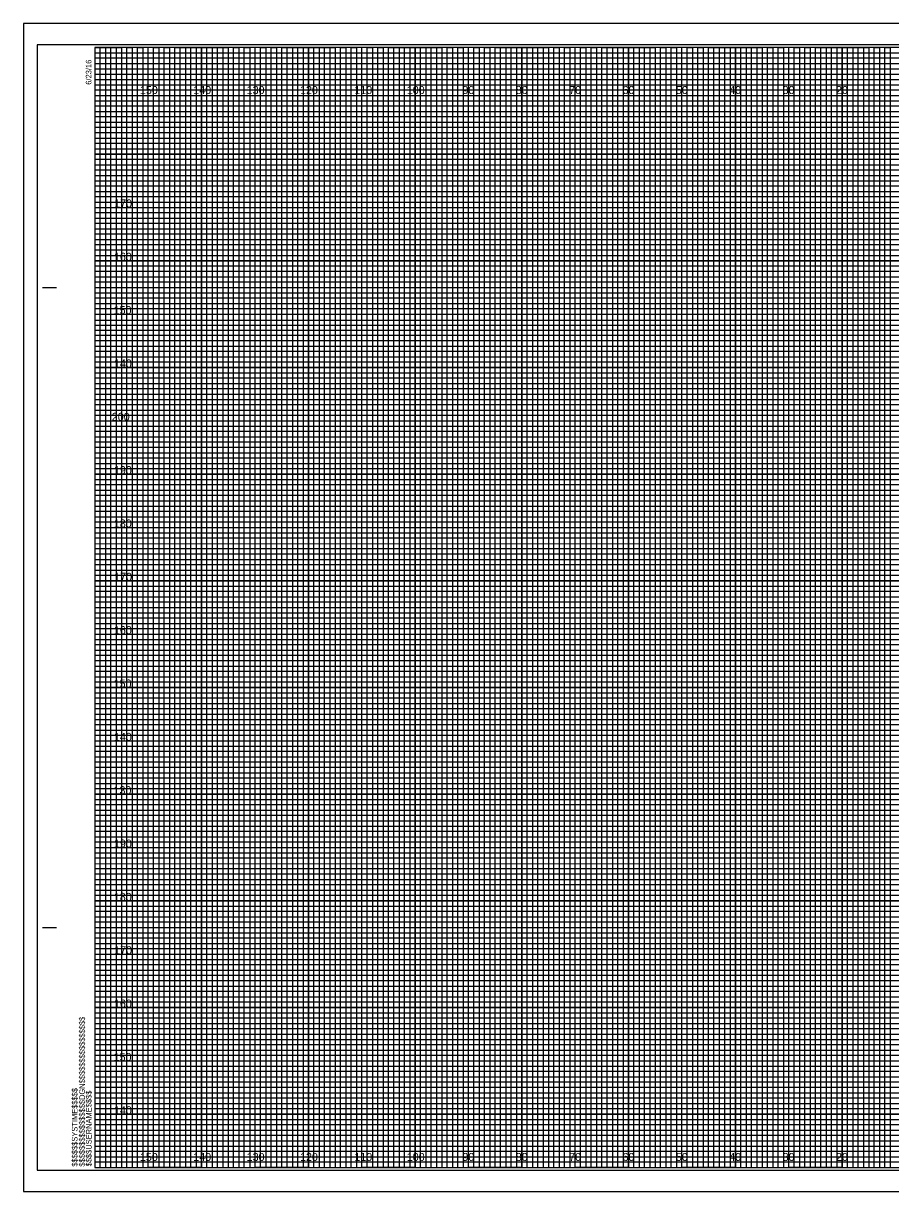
# Model space of a CAD drawing. Extents: x -13 to 323, y -5 to 654.
# Drawn here: x -13.4 to 149.1, y -4.5 to 214.5 of the extents above; entities that cross this region are included whole.
import ezdxf

# ---------------------------------------------------------------- set-up
doc = ezdxf.new("R2010")
doc.units = 0
for name, color, linetype in [('Exist Cross Section Cell', 7, 'Continuous'), ('Exist XS Center Line Elevation Label', 7, 'Continuous'), ('Exist XS Ground Line', 7, 'Continuous'), ('Prop CMT Guardrail Graphics', 7, 'Continuous'), ('Prop CMT Pvmt Course 1', 7, 'Continuous'), ('Prop CMT Pvmt Course 2', 7, 'Continuous'), ('Prop CMT Pvmt Course 3', 7, 'Continuous'), ('Prop CMT Shld Paved Course 1', 7, 'Continuous'), ('Prop CMT Shld Paved Course 2', 7, 'Continuous'), ('Prop CMT Subgrade Earthwork', 7, 'Continuous'), ('Scratch_Level_0', 7, 'Continuous')]:
    doc.layers.add(name, color=color, linetype=linetype)

msp = doc.modelspace()

# ---------------------------------------------------------------- linework, layer by layer
at = {"layer": 'Exist XS Center Line Elevation Label'}
for points in [[(0, 210), (5, 210), (5, 0), (15, 0), (15, 210), (25, 210), (25, 0), (35, 0), (35, 210), (45, 210), (45, 0), (55, 0), (55, 210), (65, 210), (65, 0), (75, 0), (75, 210), (85, 210), (85, 0), (95, 0), (95, 210), (105, 210), (105, 0), (115, 0), (115, 210), (125, 210), (125, 0), (135, 0), (135, 210), (145, 210), (145, 0), (155, 0)], [(0, 205), (275, 205)], [(0, 185), (320, 185), (320, 195), (0, 195)], [(0, 165), (320, 165), (320, 175), (0, 175)], [(0, 145), (320, 145), (320, 155), (0, 155)], [(0, 125), (320, 125), (320, 135), (0, 135)], [(0, 105), (320, 105), (320, 115), (0, 115)], [(0, 85), (320, 85), (320, 95), (0, 95)], [(0, 65), (320, 65), (320, 75), (0, 75)], [(0, 45), (320, 45), (320, 55), (0, 55)], [(0, 25), (320, 25), (320, 35), (0, 35)], [(0, 5), (320, 5), (320, 15), (0, 15)]]:
    msp.add_lwpolyline(points, dxfattribs=at)
at = {"layer": 'Exist XS Ground Line'}
for p, q in [((10, 210), (0, 210)), ((10, 0), (10, 210)), ((30, 210), (20, 210)), ((20, 210), (20, 0)), ((30, 0), (30, 210)), ((50, 210), (40, 210)), ((40, 210), (40, 0)), ((50, 0), (50, 210)), ((70, 210), (60, 210)), ((60, 210), (60, 0)), ((70, 0), (70, 210)), ((90, 210), (80, 210)), ((80, 210), (80, 0)), ((90, 0), (90, 210)), ((110, 210), (100, 210)), ((100, 210), (100, 0)), ((110, 0), (110, 210)), ((130, 210), (120, 210)), ((120, 210), (120, 0)), ((130, 0), (130, 210)), ((150, 210), (140, 210)), ((140, 210), (140, 0)), ((20, 0), (10, 0)), ((40, 0), (30, 0)), ((60, 0), (50, 0)), ((80, 0), (70, 0)), ((100, 0), (90, 0)), ((120, 0), (110, 0)), ((140, 0), (130, 0))]:
    msp.add_line(p, q, dxfattribs=at)
for points in [[(0, 200), (320, 200), (320, 190), (0, 190)], [(0, 180), (320, 180), (320, 170), (0, 170)], [(0, 160), (320, 160), (320, 150), (0, 150)], [(0, 140), (320, 140), (320, 130), (0, 130)], [(0, 120), (320, 120), (320, 110), (0, 110)], [(0, 100), (320, 100), (320, 90), (0, 90)], [(0, 80), (320, 80), (320, 70), (0, 70)], [(0, 60), (320, 60), (320, 50), (0, 50)], [(0, 40), (320, 40), (320, 30), (0, 30)], [(0, 20), (320, 20), (320, 10), (0, 10)]]:
    msp.add_lwpolyline(points, dxfattribs=at)
at = {"layer": 'Prop CMT Pvmt Course 1'}
for p, q in [((323.3, 214.5), (-13.4, 214.5)), ((-13.4, 214.5), (-13.4, -4.5)), ((-13.4, -4.5), (323.3, -4.5))]:
    msp.add_line(p, q, dxfattribs=at)
at = {"layer": 'Prop CMT Pvmt Course 2'}
msp.add_lwpolyline([(-13.4, -4.5), (323.3, -4.5), (323.3, 214.5), (-13.4, 214.5)], close=True, dxfattribs=at)
at = {"layer": 'Prop CMT Pvmt Course 3'}
msp.add_lwpolyline([(-10.8, -0.5), (322.4, -0.5), (322.4, 210.5), (-10.8, 210.5)], close=True, dxfattribs=at)
at = {"layer": 'Prop CMT Shld Paved Course 1'}
for p, q in [((-9.8, 165), (-7.3, 165)), ((-9.7, 165), (-7.2, 165)), ((-9.8, 45), (-7.3, 45)), ((-9.7, 45), (-7.2, 45)), ((0, 0), (0, 0)), ((0, 0), (0, 0)), ((0, 0), (0, 0)), ((0, 0), (0, 0)), ((0, 0), (0, 0)), ((0, 0), (0, 0)), ((0, 0), (0, 0))]:
    msp.add_line(p, q, dxfattribs=at)
msp.add_lwpolyline([(320, 210), (0, 210), (0, 0), (320, 0)], close=True, dxfattribs=at)
at = {"layer": 'Prop CMT Shld Paved Course 2'}
for points in [[(0, 0), (1, 0), (1, 210), (2, 210), (2, 0)], [(2, 0), (3, 0), (3, 210), (4, 210), (4, 0)], [(5, 0), (6, 0), (6, 210), (7, 210), (7, 0)], [(7, 0), (8, 0), (8, 210), (9, 210), (9, 0)], [(10, 0), (11, 0), (11, 210), (12, 210), (12, 0)], [(12, 0), (13, 0), (13, 210), (14, 210), (14, 0)], [(15, 0), (16, 0), (16, 210), (17, 210), (17, 0)], [(17, 0), (18, 0), (18, 210), (19, 210), (19, 0)], [(20, 0), (21, 0), (21, 210), (22, 210), (22, 0)], [(22, 0), (23, 0), (23, 210), (24, 210), (24, 0)], [(25, 0), (26, 0), (26, 210), (27, 210), (27, 0)], [(27, 0), (28, 0), (28, 210), (29, 210), (29, 0)], [(30, 0), (31, 0), (31, 210), (32, 210), (32, 0)], [(32, 0), (33, 0), (33, 210), (34, 210), (34, 0)], [(35, 0), (36, 0), (36, 210), (37, 210), (37, 0)], [(37, 0), (38, 0), (38, 210), (39, 210), (39, 0)], [(40, 0), (41, 0), (41, 210), (42, 210), (42, 0)], [(42, 0), (43, 0), (43, 210), (44, 210), (44, 0)], [(45, 0), (46, 0), (46, 210), (47, 210), (47, 0)], [(47, 0), (48, 0), (48, 210), (49, 210), (49, 0)], [(50, 0), (51, 0), (51, 210), (52, 210), (52, 0)], [(52, 0), (53, 0), (53, 210), (54, 210), (54, 0)], [(55, 0), (56, 0), (56, 210), (57, 210), (57, 0)], [(57, 0), (58, 0), (58, 210), (59, 210), (59, 0)], [(60, 0), (61, 0), (61, 210), (62, 210), (62, 0)], [(62, 0), (63, 0), (63, 210), (64, 210), (64, 0)], [(65, 0), (66, 0), (66, 210), (67, 210), (67, 0)], [(67, 0), (68, 0), (68, 210), (69, 210), (69, 0)], [(70, 0), (71, 0), (71, 210), (72, 210), (72, 0)], [(72, 0), (73, 0), (73, 210), (74, 210), (74, 0)], [(75, 0), (76, 0), (76, 210), (77, 210), (77, 0)], [(77, 0), (78, 0), (78, 210), (79, 210), (79, 0)], [(80, 0), (81, 0), (81, 210), (82, 210), (82, 0)], [(82, 0), (83, 0), (83, 210), (84, 210), (84, 0)], [(85, 0), (86, 0), (86, 210), (87, 210), (87, 0)], [(87, 0), (88, 0), (88, 210), (89, 210), (89, 0)], [(90, 0), (91, 0), (91, 210), (92, 210), (92, 0)], [(92, 0), (93, 0), (93, 210), (94, 210), (94, 0)], [(95, 0), (96, 0), (96, 210), (97, 210), (97, 0)], [(97, 0), (98, 0), (98, 210), (99, 210), (99, 0)], [(100, 0), (101, 0), (101, 210), (102, 210), (102, 0)], [(102, 0), (103, 0), (103, 210), (104, 210), (104, 0)], [(105, 0), (106, 0), (106, 210), (107, 210), (107, 0)], [(107, 0), (108, 0), (108, 210), (109, 210), (109, 0)], [(110, 0), (111, 0), (111, 210), (112, 210), (112, 0)], [(112, 0), (113, 0), (113, 210), (114, 210), (114, 0)], [(115, 0), (116, 0), (116, 210), (117, 210), (117, 0)], [(117, 0), (118, 0), (118, 210), (119, 210), (119, 0)], [(120, 0), (121, 0), (121, 210), (122, 210), (122, 0)], [(122, 0), (123, 0), (123, 210), (124, 210), (124, 0)], [(125, 0), (126, 0), (126, 210), (127, 210), (127, 0)], [(127, 0), (128, 0), (128, 210), (129, 210), (129, 0)], [(130, 0), (131, 0), (131, 210), (132, 210), (132, 0)], [(132, 0), (133, 0), (133, 210), (134, 210), (134, 0)], [(135, 0), (136, 0), (136, 210), (137, 210), (137, 0)], [(137, 0), (138, 0), (138, 210), (139, 210), (139, 0)], [(140, 0), (141, 0), (141, 210), (142, 210), (142, 0)], [(142, 0), (143, 0), (143, 210), (144, 210), (144, 0)], [(145, 0), (146, 0), (146, 210), (147, 210), (147, 0)], [(147, 0), (148, 0), (148, 210), (149, 210), (149, 0)]]:
    msp.add_lwpolyline(points, dxfattribs=at)
at = {"layer": 'Prop CMT Subgrade Earthwork'}
for p, q in [((10, 0), (10, 210)), ((20, 0), (20, 210)), ((30, 0), (30, 210)), ((40, 0), (40, 210)), ((50, 0), (50, 210)), ((60, 0), (60, 210)), ((70, 0), (70, 210)), ((80, 0), (80, 210)), ((90, 0), (90, 210)), ((100, 0), (100, 210)), ((110, 0), (110, 210)), ((120, 0), (120, 210)), ((130, 0), (130, 210)), ((140, 0), (140, 210)), ((0, 200), (320, 200)), ((0, 190), (320, 190)), ((0, 180), (320, 180)), ((0, 170), (320, 170)), ((0, 160), (320, 160)), ((0, 150), (320, 150)), ((0, 140), (320, 140)), ((0, 130), (320, 130)), ((0, 120), (320, 120)), ((0, 110), (320, 110)), ((0, 100), (320, 100)), ((0, 90), (320, 90)), ((0, 80), (320, 80)), ((0, 70), (320, 70)), ((0, 60), (320, 60)), ((0, 50), (320, 50)), ((0, 40), (320, 40)), ((0, 30), (320, 30)), ((0, 20), (320, 20)), ((0, 10), (320, 10))]:
    msp.add_line(p, q, dxfattribs=at)
at = {"layer": 'Scratch_Level_0'}
for p, q in [((0, 209), (260, 209)), ((260, 207.98), (0, 207.98)), ((0, 207.98), (0, 207)), ((0, 207), (260, 207)), ((260, 205.89), (0, 205.89)), ((0, 205.89), (0, 204)), ((0, 204), (320, 204))]:
    msp.add_line(p, q, dxfattribs=at)
for points in [[(0, 203), (270, 203), (320, 203), (320, 202), (0, 202)], [(0, 201), (320, 201), (320, 199), (0, 199)], [(0, 198), (320, 198), (320, 197), (0, 196.98)], [(0, 196), (320, 196), (320, 194), (0, 194)], [(0, 193), (320, 193), (320, 192), (0, 192)], [(0, 191), (320, 191), (320, 189), (0, 189)], [(0, 188), (320, 188), (320, 187), (0, 187)], [(0, 186), (320, 186), (320, 184), (0, 184)], [(0, 183), (320, 183), (320, 182), (0, 182)], [(0, 181), (320, 181), (320, 179), (0, 179)], [(0, 178), (320, 178), (320, 177), (0, 177)], [(0, 176), (320, 176), (320, 173.95), (320, 173), (320, 172), (0, 172)], [(0, 174), (320, 174), (320, 173), (0, 173)], [(0, 171), (320, 171), (320, 169), (0, 169.03)], [(0, 169.03), (320, 169), (320, 168), (0, 168)], [(0, 167), (320, 167), (320, 166), (0, 166)], [(0, 164), (320, 164), (320, 163), (0, 163)], [(0, 162), (320, 162), (320, 161), (0, 161)], [(-0.07, 158.89), (320, 158.89), (320, 157.88), (-0.07, 157.88)], [(0, 157), (320, 157), (320, 156), (0, 156)], [(0, 154), (320, 154), (320, 153), (0, 153)], [(0, 152), (320, 152), (320, 151), (0, 151)], [(0, 149), (320, 149), (320, 148), (0, 148)], [(0, 147), (320, 147), (320, 146), (0, 146)], [(0, 144), (320, 144), (320, 143), (0, 143)], [(0, 142), (320, 142), (320, 141), (0, 141)], [(0, 139), (320, 139), (319.99, 137.98), (0, 138)], [(0, 137), (320, 137), (320, 136), (0, 136)], [(0, 134), (320, 134), (320, 133), (0, 133)], [(0, 132), (320, 132), (320, 131), (0, 131)], [(0, 129), (320, 129), (320, 128), (0, 128)], [(0, 127), (320, 127), (320, 126), (0, 126)], [(0, 124), (320, 124), (320, 123), (0, 123)], [(0, 122), (320, 122), (320, 121), (0, 121)], [(0, 119), (320, 119), (320, 118), (0, 118)], [(0, 116.99), (320.07, 116.91), (320, 116), (0, 116)], [(0, 114), (320, 114), (320, 113), (0, 113)], [(0, 112), (320, 112), (320, 111), (0, 111)], [(0, 109), (320, 109), (320, 108), (0, 108)], [(0, 107), (320, 107), (320, 106), (0, 106)], [(0, 104), (320, 104), (320, 103), (0, 103)], [(0, 102), (320, 102), (320, 101), (0, 101)], [(0, 99), (320, 99), (320, 98), (0, 98)], [(0, 97), (320, 97), (320, 96), (0, 96)], [(0, 94), (320, 94), (320, 93), (0, 93)], [(0, 92), (320, 92), (320, 91), (0, 91)], [(0, 89), (320, 89), (320, 88), (0, 88)], [(0, 87), (320, 87), (320, 86), (0, 86)], [(0, 84), (320, 84), (320, 83), (0, 83)], [(0, 82), (320, 82), (320, 81), (0, 81)], [(0, 79), (320, 79), (319.99, 77.98), (0, 78)], [(0, 77), (320, 77), (320, 76), (0, 76)], [(0, 74), (320, 74), (320, 73), (0, 73)], [(0, 72), (320, 72), (320, 71), (0, 71)], [(0, 69), (320, 69), (320, 68), (0, 68)], [(0, 67), (320, 67), (320, 66), (0, 66)], [(0, 64), (320, 64), (320, 63), (0, 63)], [(0, 62), (320, 62), (320, 61), (0, 61)], [(0, 59), (320, 59), (320, 58), (0, 58)], [(0, 56.99), (320.07, 56.91), (320, 56), (0, 56)], [(0, 54), (320, 54), (320, 53), (0, 53)], [(0, 52), (320, 52), (320, 51), (0, 51)], [(0, 49), (320, 49), (320, 48), (0, 48)], [(0, 47), (320, 47), (320, 46), (0, 46)], [(0, 44), (320, 44), (320, 43), (0, 43)], [(0, 42), (320, 42), (320, 41), (0, 41)], [(0, 39), (320, 39), (320, 38), (0, 38)], [(0, 37), (320, 37), (320, 36), (0, 36)], [(0, 34), (320, 34), (320, 33), (0, 33)], [(0, 32), (320, 32), (320, 31), (0, 31)], [(0, 29), (320, 29), (320, 28), (0, 28)], [(0, 27), (320, 27), (320, 26), (0, 26)], [(0, 24), (320, 24), (320, 23), (0, 23)], [(0, 22), (320, 22), (320, 21), (0, 21)], [(0, 19), (320, 19), (320, 18), (0, 18)], [(0, 17), (320, 17), (320, 16), (0, 16)], [(0, 14), (320, 14), (320, 13), (0, 13)], [(0, 12), (320, 12), (320, 11), (0, 11)], [(0, 9), (320, 9), (320, 8), (0, 8)], [(0, 7), (320, 7), (320, 6), (0, 6)], [(0, 4), (320, 4), (320, 3), (0, 3)], [(0, 2), (320, 2), (320, 1), (0, 1)]]:
    msp.add_lwpolyline(points, dxfattribs=at)

# ---------------------------------------------------------------- texts
at = {"layer": 'Exist Cross Section Cell'}
for s, p in [('150', (8.44, 201.25)), ('140', (18.44, 201.25)), ('130', (28.44, 201.25)), ('120', (38.44, 201.25)), ('110', (48.62, 201.25)), ('100', (58.44, 201.25)), ('90', (68.86, 201.25)), ('80', (78.86, 201.25)), ('70', (88.86, 201.25)), ('60', (98.86, 201.25)), ('50', (108.86, 201.25)), ('40', (118.86, 201.25)), ('30', (128.86, 201.25)), ('20', (138.86, 201.25)), ('150', (8.44, 1.25)), ('140', (18.44, 1.25)), ('130', (28.44, 1.25)), ('120', (38.44, 1.25)), ('110', (48.62, 1.25)), ('100', (58.44, 1.25)), ('90', (68.86, 1.25)), ('80', (78.86, 1.25)), ('70', (88.86, 1.25)), ('60', (98.86, 1.25)), ('50', (108.86, 1.25)), ('40', (118.86, 1.25)), ('30', (128.86, 1.25)), ('20', (138.86, 1.25))]:
    msp.add_text(s, height=1.5, dxfattribs=at).set_placement(p)
at = {"layer": 'Prop CMT Guardrail Graphics'}
for s, p in [('170', (3.61, 180)), ('160', (3.57, 170)), ('150', (3.52, 160)), ('140', (3.57, 150)), ('200', (3.17, 140)), ('190', (3.57, 130)), ('180', (3.55, 120)), ('170', (3.61, 110)), ('160', (3.57, 100)), ('150', (3.52, 90)), ('140', (3.57, 80)), ('130', (3.49, 70)), ('190', (3.57, 60)), ('180', (3.55, 50)), ('170', (3.61, 40)), ('160', (3.57, 30)), ('150', (3.52, 20)), ('140', (3.57, 10))]:
    msp.add_text(s, height=1.5, dxfattribs=at).set_placement(p)
at = {"layer": 'Prop CMT Shld Paved Course 1'}
for s, p in [('6/23/16', (-0.65, 203)), ('$$$$$$$$$$$$$$$$DGN$$$$$$$$$$$$$$$$', (-1.88, 0.18)), ('$$$$$$SYSTIME$$$$$', (-3.26, 0.18)), ('$$$$USERNAME$$$$', (-0.62, 0.23))]:
    msp.add_text(s, height=1.05, rotation=90, dxfattribs=at).set_placement(p)

doc.saveas('drawing.dxf')
